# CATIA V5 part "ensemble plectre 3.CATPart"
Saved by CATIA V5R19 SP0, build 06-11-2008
Part number: equerre
Bounding box of the stored display mesh (mm): x 0 to 25, y -46 to -8.004, z 12.5 to 37.5
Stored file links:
  I:\mediator\ensemble plectre 3.CATPart
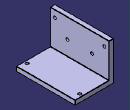
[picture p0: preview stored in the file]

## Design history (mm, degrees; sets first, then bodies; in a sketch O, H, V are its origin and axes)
Body1 (main body)
  Sketch1 on yz-plane, origin (0, 0, 0), H (0, 1, 0), V (0, 0, 1)
    line L1 (-46, 37.5005) -> (-8.004, 37.5005)
    line L2 (-8.004, 37.5005) -> (-8.004, 12.4995)
    line L3 (-8.004, 12.4995) -> (-46, 12.4995)
    line L4 (-46, 12.4995) -> (-46, 37.5005)
    construction line L5 (-27.002, 45) -> (-27.002, 7)
    circle A1 centre (-11.002, 33) radius 1
    point P7 (-11.002, 33)
    circle A2 centre (-43.002, 33) radius 1
    circle A3 centre (-19.002, 24.9995) radius 1
    point P9 (-19.002, 24.9995)
    circle A4 centre (-35.002, 24.9995) radius 1
    length L1 = 37.996
    length L2 = 25.001
    distance L5 L2 = 18.998
    radius A3 = 1
    distance P9 L1 = 12.501
    distance P9 L2 = 10.998
    distance L2 P7 = 2.998
    distance P7 L1 = 4.5005
    horizontal: L1 H, L3 H
    vertical: L2 V, L4 V, L5 V
    symmetry: A1 A2 L5, A3 A4 L5
  Pad1: profile Sketch1, direction (1, 0, 0), length 3
  Sketch2 on end face of Pad1, origin (3, 0, 0), H (0, 1, 0), V (0, 0, 1)
    line L1 (-46, 12.4995) -> (-8.004, 12.4995)
    line L2 (-8.004, 12.4995) -> (-8.004, 15.4995)
    line L3 (-8.004, 15.4995) -> (-46, 15.4995)
    line L4 (-46, 15.4995) -> (-46, 12.4995)
    reference projected line E1 (-8.004, 12.4995) -> (-8.004, 37.5005) from edge [face of Pad1 from Sketch1.L2 | end face of Pad1]
    reference projected line E2 (-46, 12.4995) -> (-8.004, 12.4995) from edge [face of Pad1 from Sketch1.L3 | end face of Pad1]
    reference projected line E3 (-46, 37.5005) -> (-46, 12.4995) from edge [face of Pad1 from Sketch1.L4 | end face of Pad1]
    distance L2 E1 = 0
    distance L1 E2 = 0
    distance L4 E3 = 0
    distance L1 L3 = 3
    horizontal: L1 H, L3 H
    vertical: L2 V, L4 V
  Pad2: profile Sketch2, direction (1, 0, 0), length 22
  Sketch3 on face of Pad2 from Sketch2.L3, origin (0, 0, 15.4995), H (1, 0, 0), V (0, 1, 0)
    circle A1 centre (20, -10.004) radius 1
    point P1 (20, -10.004)
    circle A2 centre (20, -44) radius 1
    point P2 (20, -44)
    reference projected line E1 (25, -8.004) -> (25, -46) from edge [face of Pad2 from Sketch2.L3 | end face of Pad2]
    reference projected line E2 (25, -8.004) -> (25, -46) from edge [face of Pad2 from Sketch2.L3 | end face of Pad2]
    reference projected line E3 (3, -46) -> (25, -46) from edge [face of Pad2 | face of Pad2 from Sketch2.L3]
    reference projected line E4 (3, -8.004) -> (25, -8.004) from edge [face of Pad2 from Sketch2.L3 | face of Pad2]
    radius A2 = 1
    radius A1 = 1
    distance P2 E1 = 5
    distance P1 E2 = 5
    distance P2 E3 = 2
    distance P1 E4 = 2
  Pocket1: profile Sketch3, direction (0, 0, -1), length 22
  Fillet1: radius 0.2, on edge [face of Pad2 from Sketch2.L3 | end face of Pad2]; edge [face of Pad2 | end face of Pad2] (x2); edge [face of Pad2 from Sketch2.L3 | face of Pad2]; edge [face of Pad2 | face of Pad2]; edge [face of Pad2 | end face of Pad1]; edge [start face of Pad1 | face of Pad2]; edge [face of Pad1 from Sketch1.L1 | face of Pad2]; face of Pad1 from Sketch1.L1; face of Pad2; edge [end face of Pad1 | face of Pad2 from Sketch2.L3]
